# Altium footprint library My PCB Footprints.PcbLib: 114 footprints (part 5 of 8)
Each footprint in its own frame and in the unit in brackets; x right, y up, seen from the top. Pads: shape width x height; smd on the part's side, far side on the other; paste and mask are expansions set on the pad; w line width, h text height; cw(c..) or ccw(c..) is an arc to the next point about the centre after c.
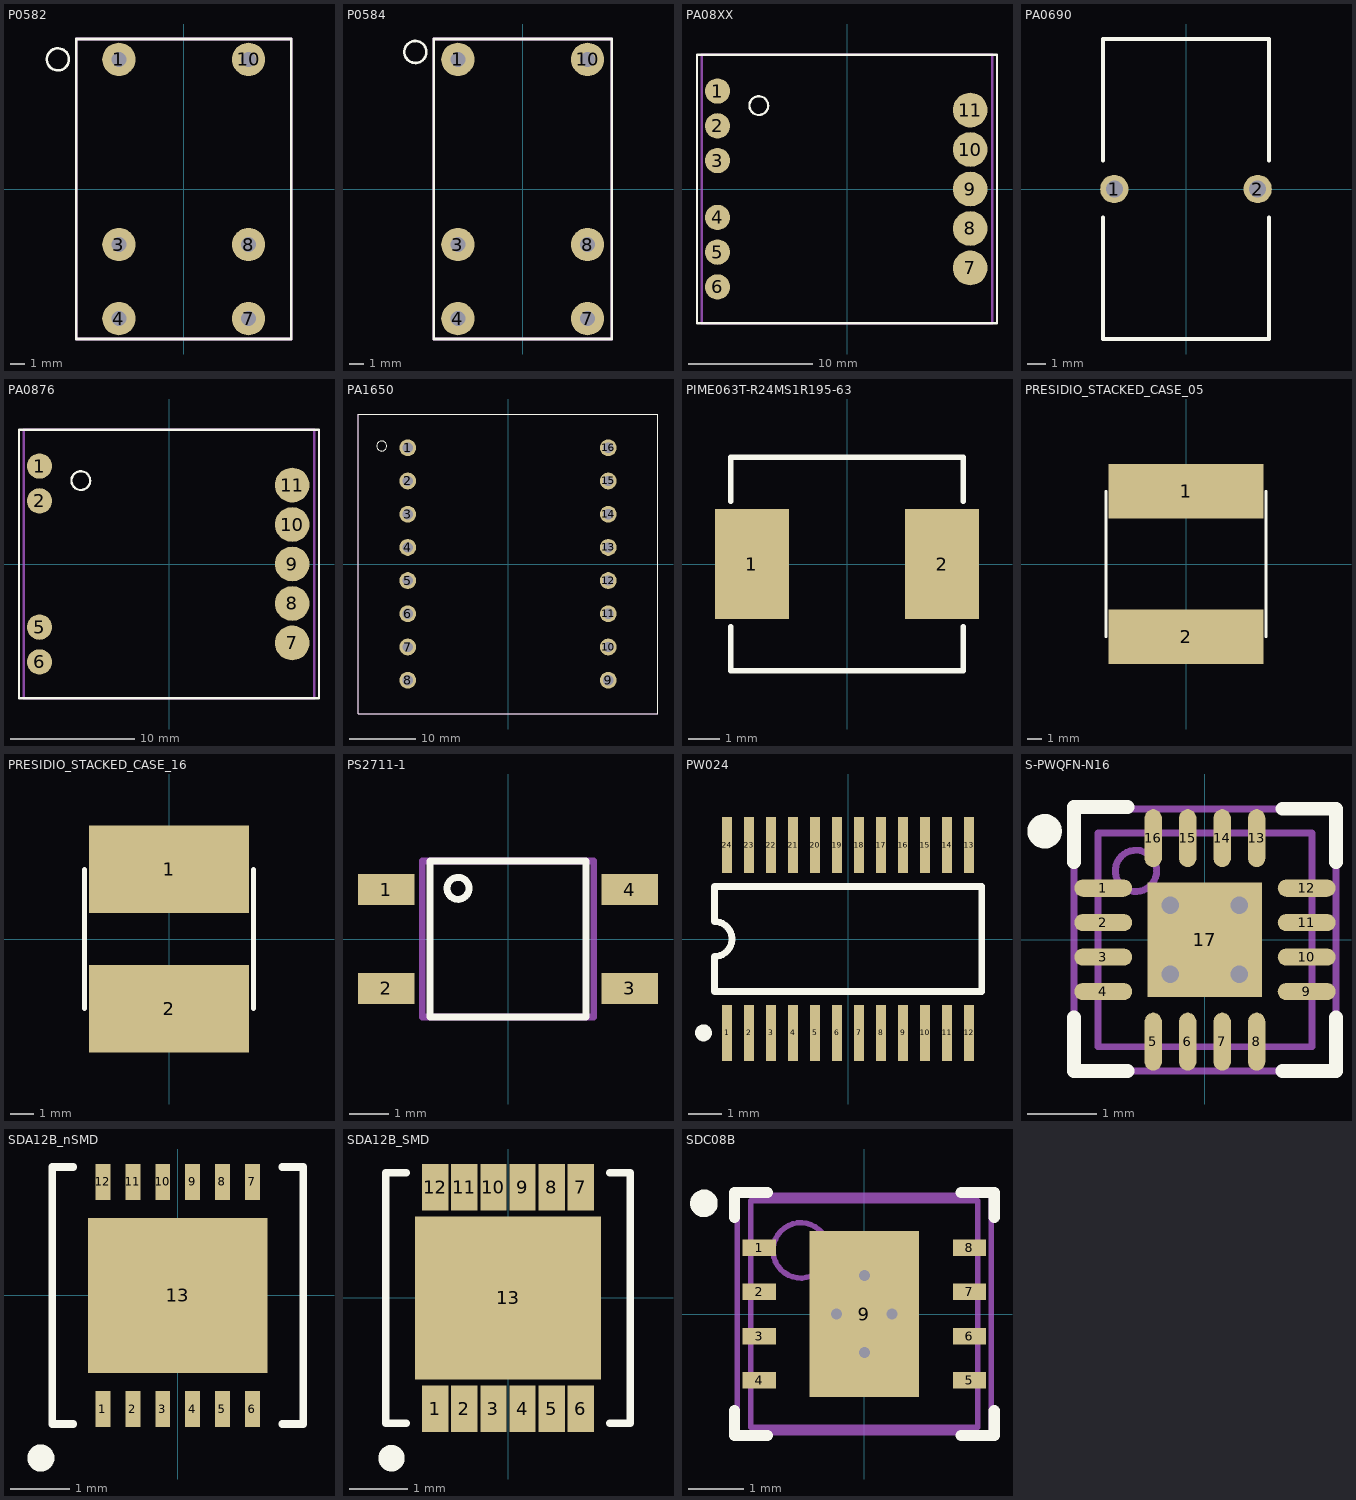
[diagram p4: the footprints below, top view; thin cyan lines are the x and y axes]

## P0582 [mil] "Pulse Offline Current SenseTransformer"
height 750
pads (6):
  round 90 hole 40: 1(-175,350) 3(-175,-150) 4(-175,-350) 7(175,-350) 8(175,-150) 10(175,350)
Top Overlay:
  circle w7: c-339.73,350 r29.73
  lines w7: -290,-405 290,-405 290,405 -290,405 -290,-405
Mechanical 5:
  text ".designator" at -48,-25 h60
Mechanical 13:
  lines w7: -290,-405 290,-405 290,405 -290,405 -290,-405
3D body: height 720, standoff 30, extent -290,-405 290,405
3D body: height 750, standoff 749, extent -260.51,316.15 -200.57,376.09

## P0584 [mil] "Pulse Offline Gate Drive Transformer"
height 750
pads (6):
  round 90 hole 40: 1(-175,350) 3(-175,-150) 4(-175,-350) 7(175,-350) 8(175,-150) 10(175,350)
Top Overlay:
  circle w7: c-289.73,370 r29.73
  lines w7: -240,-405 240,-405 240,405 -240,405 -240,-405
Mechanical 5:
  text ".designator" at -48,-25 h60
Mechanical 13:
  lines w7: -240,-405 240,-405 240,405 -240,405 -240,-405
3D body: height 720, standoff 30, extent -240,-405 240,405
3D body: height 750, standoff 749, extent -216.09,320.57 -156.15,380.51

## PA08XX [mil] "Recommended land pattern for Pulse PA08xxNL series of transformers"
height 381.89
pads (11):
  round 80 smd: 1(-410,310) 2(-410,200) 3(-410,90) 4(-410,-90) 5(-410,-200) 6(-410,-310)
  round 110 smd: 7(390,-250) 8(390,-125) 9(390,0) 10(390,125) 11(390,250)
Top Overlay:
  circle w7: c-279.27,264 r29.73
  lines w7: -475,-425 -475,0 -475,425 0,425 475,425 475,0 475,-425 0,-425 -475,-425
Mechanical 5:
  text ".designator" at -48,-25 h60
Mechanical 13:
  lines w7: -460,-425 460,-425 460,425 -460,425 -460,-425
3D body: height 381.89, standoff 0, extent -459.98,-424.98 459.98,424.98
3D body: height 381.93, standoff 381.89, extent -309.24,234.03 -249.3,293.97

## PA0690 [mm] "Inductor, Toroid, Thru-Hole, Iron Powder; Body 15.9 x 8.8 mm (LxW max) Pin Spacing 7.6 mm (typ)"
height 13.8
pads (2):
  round 1.5 hole 0.9: 1(-3.8,0) 2(3.8,0)
Top Overlay:
  lines w0.2: -4.4,-1.5 -4.4,-7.95 4.4,-7.95 4.4,-1.5 ; -4.4,1.5 -4.4,7.95 4.4,7.95 4.4,1.5

## PA0876 [mil] "Recommended land pattern for Pulse PA0876NL transformer"
height 381.89
pads (9):
  round 80 smd: 1(-410,310) 2(-410,200) 5(-410,-200) 6(-410,-310)
  round 110 smd: 7(390,-250) 8(390,-125) 9(390,0) 10(390,125) 11(390,250)
Top Overlay:
  circle w7: c-279.27,264 r29.73
  lines w7: -475,-425 -475,0 -475,425 0,425 475,425 475,0 475,-425 0,-425 -475,-425
Mechanical 5:
  text ".designator" at -48,-25 h60
Mechanical 13:
  lines w7: -460,-425 460,-425 460,425 -460,425 -460,-425
3D body: height 381.89, standoff 0, extent -459.98,-424.98 459.98,424.98
3D body: height 381.93, standoff 381.89, extent -309.24,234.03 -249.3,293.97

## PA1650 [mil] "Pulse Phase Shifted Full Bridge Transformer"
height 1420
pads (16):
  round 100 hole 60: 1(-595,689.5) 2(-595,492.5) 3(-595,295.5) 4(-595,98.5) 5(-595,-98.5) 6(-595,-295.5) 7(-595,-492.5) 8(-595,-689.5) 9(595,-689.5) 10(595,-492.5) 11(595,-295.5) 12(595,-98.5) 13(595,98.5) 14(595,295.5) 15(595,492.5) 16(595,689.5)
Top Overlay:
  circle w7: c-749.73,700 r29.73
  lines w7: -890,-890 -890,0 -890,890 0,890 890,890 890,0 890,-890 0,-890 -890,-890
Mechanical 5:
  text ".designator" at -48,-25 h60
Mechanical 13:
  lines w7: -890,-890 890,-890 890,890 -890,890 -890,-890
3D body: height 1270, standoff 150, extent -890,-890 890,890
3D body: height 1420, standoff 1419, extent -778.06,671.46 -718.12,731.4

## PCBComponent_1 [mm]

## PIME063T-R24MS1R195-63 [mm] "Cyntec land pattern"
height 3
pads (2):
  rect 2.35x3.5 smd: 1(-3.025,0) 2(3.025,0)
Top Overlay:
  lines w0.178: -3.7,-2 -3.7,-3.4 0,-3.4 3.7,-3.4 3.7,-2 ; -3.7,2 -3.7,3.4 0,3.4 3.7,3.4 3.7,2
Mechanical 5:
  text ".Designator" at -1.524,-0.508 h1.02
3D body: height 3, standoff 0, extent -3.7,-3.4 3.7,3.4

## PRESIDIO_STACKED_CASE_05 [mm]
pads (2):
  rect 10.795x3.81 smd: 1(0,5.08) 2(0,-5.08)
Top Overlay:
  lines w0.2: -5.588,-5.08 -5.588,5.08 ; 5.588,-5.08 5.588,5.08

## PRESIDIO_STACKED_CASE_16 [mil]
pads (2):
  rect 275x150 smd: 1(0,120) 2(0,-120)
Top Overlay:
  lines w7.87: -145,-120 -145,120 ; 145,-120 145,120

## PS2711-1 [mm] "NEC optocoupler"
height 2.1
pads (4):
  rect 1.45x0.8 smd: 1(-3.125,1.27) 2(-3.125,-1.27) 3(3.125,-1.27) 4(3.125,1.27)
Top Overlay:
  circle w0.178: c-1.283,1.3 r0.283
  lines w0.178: -2,-2 0.5,-2 2,-2 2,0 2,2 -0.5,2 -2,2 -2,0 -2,-2
Mechanical 13:
  lines w0.178: -2.2,-2 0,-2 2.2,-2 2.2,0 2.2,2 0,2 -2.2,2 -2.2,0 -2.2,-2
3D body: height 2.1, standoff 0, extent -2.199,-2 2.199,2
3D body: height 2.1, standoff 2, extent -1.57,1.002 -0.994,1.578

## PW024 [mm] "Shrink Small Outline; 24 Leads; Body Width 4.4 mm; Pitch 0.65 mm"
height 1.2
pads (24):
  rect 0.3x1.65 smd: 1(-3.575,-2.775) 2(-2.925,-2.775) 3(-2.275,-2.775) 4(-1.625,-2.775) 5(-0.975,-2.775) 6(-0.325,-2.775) 7(0.325,-2.775) 8(0.975,-2.775) 9(1.625,-2.775) 10(2.275,-2.775) 11(2.925,-2.775) 12(3.575,-2.775) 13(3.575,2.775) 14(2.925,2.775) 15(2.275,2.775) 16(1.625,2.775) 17(0.975,2.775) 18(0.325,2.775) 19(-0.325,2.775) 20(-0.975,2.775) 21(-1.625,2.775) 22(-2.275,2.775) 23(-2.925,2.775) 24(-3.575,2.775)
Top Overlay:
  circle w0.25: c-4.275,-2.775 r0.125
  lines w0.2: -3.95,-1.55 3.95,-1.55 3.95,1.55 -3.95,1.55 -3.95,0.517 cw(c-3.95,0) -3.95,-0.517 -3.95,-1.55
Mechanical 5:
  text ".Designator" at -2.54,-0.508 h1.02

## S-PWQFN-N16 [mm] "QFN, 16-Leads, Body 3x3mm, Pitch 0.5mm, TI Recommended"
height 0.8
pads (17):
  oval 0.84x0.25 smd paste-0.025 mask+0.07: 1(-1.475,0.75) 2(-1.475,0.25) 3(-1.475,-0.25) 4(-1.475,-0.75) 9(1.475,-0.75) 10(1.475,-0.25) 11(1.475,0.25) 12(1.475,0.75)
  oval 0.25x0.84 smd paste-0.025 mask+0.07: 5(-0.75,-1.475) 6(-0.25,-1.475) 7(0.25,-1.475) 8(0.75,-1.475) 13(0.75,1.475) 14(0.25,1.475) 15(-0.25,1.475) 16(-0.75,1.475)
  rect 1.66x1.66 smd paste-1.3 mask+0.051: 17(0,0)
via 0.5,-0.5 diameter 0.508 hole 0.254
via -0.5,0.5 diameter 0.508 hole 0.254
via 0.5,0.5 diameter 0.508 hole 0.254
via -0.5,-0.5 diameter 0.508 hole 0.254
Top Overlay:
  circle w0.25: c-2.325,1.575 r0.125
  lines w0.2: -1.9,-1.125 -1.9,-1.9 -1.125,-1.9 ; -1.9,1.125 -1.9,1.925 -1.125,1.925 ; 1.125,-1.9 1.9,-1.9 1.9,-1.125 ; 1.125,1.9 1.9,1.9 1.9,1.125
Top Paste:
  rectangle: 0.1,0.1 0.8,0.8
  region: -0.1,0.8 -0.8,0.8 -0.8,0.1 -0.1,0.1
  region: -0.1,-0.1 -0.8,-0.1 -0.8,-0.8 -0.1,-0.8
  rectangle: 0.1,-0.8 0.8,-0.1
Mechanical 5:
  text ".Designator" at -1.524,-0.508 h1.02
Mechanical 13:
  circle w0.1: c-1,1 r0.3
  lines w0.1: -1.55,-1.55 1.55,-1.55 1.55,1.55 -1.55,1.55 -1.55,-1.55
Mechanical 15:
  lines w0.1: -0.5,0 0.5,0 ; 0,-0.5 0,0.5 ; -1.9,-1.9 1.9,-1.9 1.9,1.9 -1.9,1.9 -1.9,-1.9
3D body: height 0.8, standoff 0, extent -1.55,-1.55 1.55,1.55

## SDA12B_nSMD [mm] "12 Pin LLP + DAP Package, Non-Soldermask Def, 4 x 4mm"
height 0.8
pads (13):
  rect 0.25x0.6 smd: 1(-1.25,-1.9) 2(-0.75,-1.9) 3(-0.25,-1.9) 4(0.25,-1.9) 5(0.75,-1.9) 6(1.25,-1.9) 7(1.25,1.9) 8(0.75,1.9) 9(0.25,1.9) 10(-0.25,1.9) 11(-0.75,1.9) 12(-1.25,1.9)
  rect 3x2.6 smd: 13(0,0)
Top Overlay:
  circle w0.254: c-2.29,-2.72 r0.1
  lines w0.127: -1.75,-2.15 -2.1,-2.15 -2.1,2.15 -1.75,2.15 ; 1.75,-2.15 2.1,-2.15 2.1,2.15 1.75,2.15
Mechanical 5:
  text ".Designator" at -1.524,-0.508 h1.02
3D body: height 0.8, standoff 0, extent -2,-2 2,2

## SDA12B_SMD [mm] "12 Pin LLP + DAP Package, Solder mask Defined, 4 x 4mm"
height 0.8
pads (13):
  rect 0.45x0.8 smd paste-0.1 mask-0.1: 1(-1.25,-1.9) 2(-0.75,-1.9) 3(-0.25,-1.9) 4(0.25,-1.9) 5(0.75,-1.9) 6(1.25,-1.9) 7(1.25,1.9) 8(0.75,1.9) 9(0.25,1.9) 10(-0.25,1.9) 11(-0.75,1.9) 12(-1.25,1.9)
  rect 3.2x2.8 smd paste-0.1 mask-0.1: 13(0,0)
Top Overlay:
  circle w0.254: c-2,-2.75 r0.1
  lines w0.127: -1.75,-2.15 -2.1,-2.15 -2.1,2.15 -1.75,2.15 ; 1.75,-2.15 2.1,-2.15 2.1,2.15 1.75,2.15
Mechanical 5:
  text ".Designator" at -1.524,-0.508 h1.02
3D body: height 0.8, standoff 0, extent -2,-2 2,2

## SDC08B [mm] "SON, 8-Leads, Body 4x4mm, Pitch 0.8mm, NSC Recommended"
height 0.8
pads (9):
  rect 0.6x0.3 smd paste-0.15 mask+0.051: 1(-1.9,1.2) 2(-1.9,0.4) 3(-1.9,-0.4) 4(-1.9,-1.2) 5(1.9,-1.2) 6(1.9,-0.4) 7(1.9,0.4) 8(1.9,1.2)
  rect 1.98x3 smd paste-1.5 mask+0.051: 9(0,0)
via 0,-0.7 diameter 0.5 hole 0.2
via 0,0.7 diameter 0.5 hole 0.2
via 0.5,0 diameter 0.5 hole 0.2
via -0.5,0 diameter 0.5 hole 0.2
Top Overlay:
  circle w0.25: c-2.9,2 r0.125
  lines w0.2: -2.35,-1.75 -2.35,-2.2 -1.75,-2.2 ; -2.35,1.75 -2.35,2.2 -1.75,2.2 ; 1.75,-2.2 2.35,-2.2 2.35,-1.75 ; 1.75,2.2 2.35,2.2 2.35,1.75
Top Paste:
  region: -1.7,1.35 -2.4,1.35 -2.4,1.05 -1.7,1.05
  region: -1.7,0.55 -2.4,0.55 -2.4,0.25 -1.7,0.25
  region: -1.7,-0.25 -2.4,-0.25 -2.4,-0.55 -1.7,-0.55
  region: -1.7,-1.05 -2.4,-1.05 -2.4,-1.35 -1.7,-1.35
  rectangle: 1.7,-1.35 2.4,-1.05
  rectangle: 1.7,-0.55 2.4,-0.25
  rectangle: 1.7,0.25 2.4,0.55
  rectangle: 1.7,1.05 2.4,1.35
  region: 0.89,-0.15 0.15,-0.15 0.15,-1.4 0.89,-1.4
  rectangle: -0.89,-1.4 -0.15,-0.15
  rectangle: -0.89,0.15 -0.15,1.4
  region: 0.89,1.4 0.15,1.4 0.15,0.15 0.89,0.15
Mechanical 5:
  text ".Designator" at -1.524,-0.508 h1.02
Mechanical 13:
  circle w0.1: c-1.15,1.15 r0.5
  lines w0.1: -2.05,-2.05 -2.05,2.05 2.05,2.05 2.05,-2.05 -2.05,-2.05
Mechanical 15:
  lines w0.1: -0.5,0 0.5,0 ; 0,-0.5 0,0.5 ; -2.3,-2.15 -2.3,2.15 2.3,2.15 2.3,-2.15 -2.3,-2.15
3D body: height 0.8, standoff 0, extent -2.05,-2.05 2.05,2.05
